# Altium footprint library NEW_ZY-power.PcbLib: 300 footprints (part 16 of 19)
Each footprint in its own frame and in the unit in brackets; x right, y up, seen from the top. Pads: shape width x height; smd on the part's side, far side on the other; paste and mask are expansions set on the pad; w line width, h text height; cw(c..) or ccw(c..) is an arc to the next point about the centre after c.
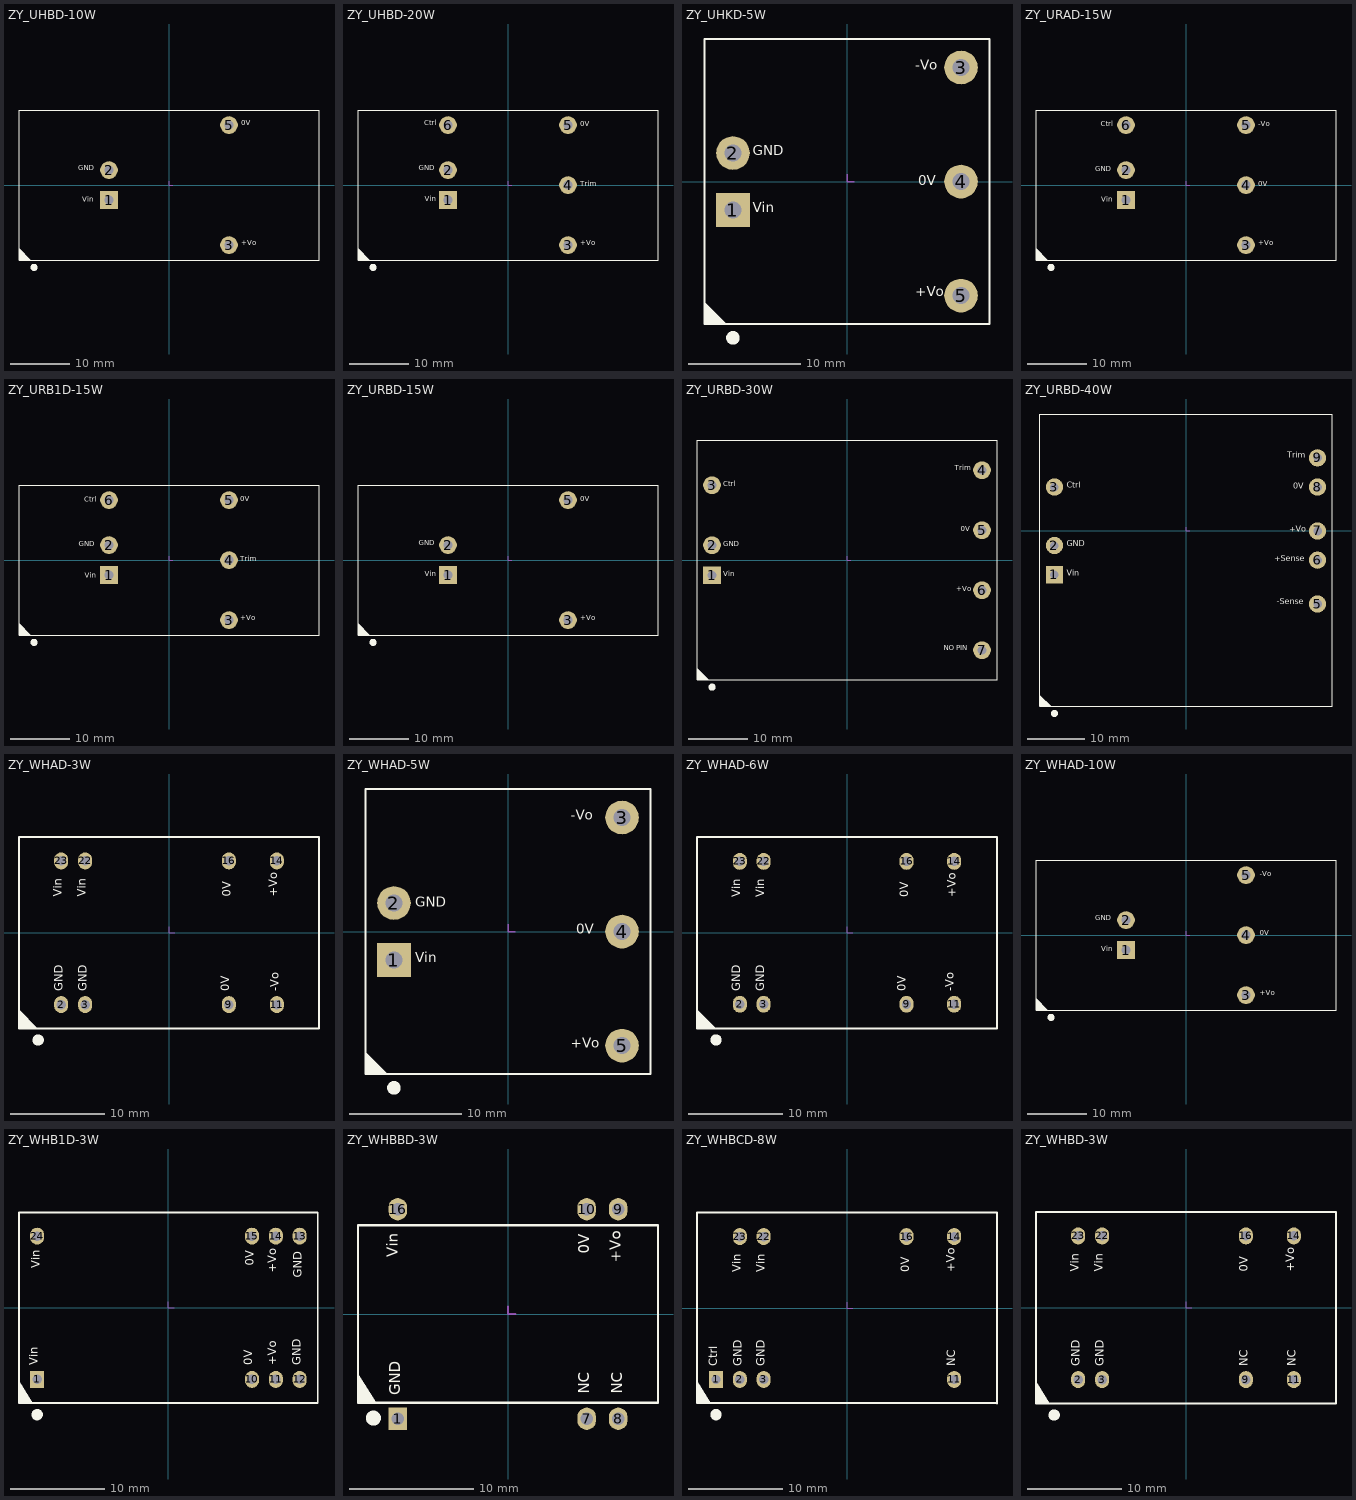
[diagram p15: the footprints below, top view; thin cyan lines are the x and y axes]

## ZY_UHBD-10W [mm]
height 12.7
pads (4):
  rect 3x3 hole 1.5: 1(-10.16,-2.54)
  round 3 hole 1.5: 2(-10.16,2.54) 3(10.16,-10.16) 5(10.16,10.16)
Top Overlay:
  circle w1: c-22.86,-13.925 r0.1
  region: -25.4,-12.7 -23.425,-12.7 -25.4,-10.725
  lines w0.2: -25.4,-12.7 -25.4,12.7 25.4,12.7 25.4,-12.7 -25.4,-12.7
  text "Vin" at -14.732,-3.175 h1.52
  text "GND" at -15.368,2.159 h1.52
  text "+Vo" at 12.192,-10.541 h1.52
  text "0V" at 12.192,9.779 h1.52
Mechanical 15:
  lines w0.127: 0,0.635 0,0 0.635,0

## ZY_UHBD-20W [mm]
pads (6):
  rect 3x3 hole 1.5: 1(-10.16,-2.54)
  round 3 hole 1.5: 2(-10.16,2.54) 3(10.16,-10.16) 4(10.16,0) 5(10.16,10.16) 6(-10.16,10.16)
Top Overlay:
  circle w1: c-22.86,-13.925 r0.1
  region: -25.4,-12.7 -23.425,-12.7 -25.4,-10.725
  lines w0.2: -25.4,-12.7 -25.4,12.7 25.4,12.7 25.4,-12.7 -25.4,-12.7
  text "+Vo" at 12.192,-10.541 h1.52
  text "0V" at 12.192,9.652 h1.52
  text "GND" at -15.113,2.159 h1.52
  text "Vin" at -14.103,-3.048 h1.52
  text "Trim" at 12.192,-0.508 h1.52
  text "Ctrl" at -14.187,9.779 h1.52
Mechanical 15:
  lines w0.127: 0,0.635 0,0 0.635,0

## ZY_UHKD-5W [mm]
pads (5):
  rect 3x3 hole 1.5: 1(-10.16,-2.54)
  round 3 hole 1.5: 2(-10.16,2.54) 3(10.16,10.16) 4(10.16,0) 5(10.16,-10.16)
Top Overlay:
  circle w1: c-10.16,-13.925 r0.1
  region: -12.7,-12.7 -10.725,-12.7 -12.7,-10.725
  lines w0.2: -12.7,-12.7 -12.7,12.7 12.7,12.7 12.7,-12.7 -12.7,-12.7
  text "Vin" at -8.382,-3.048 h1.52
  text "GND" at -8.382,2.032 h1.52
  text "0V" at 6.35,-0.635 h1.52
  text "-Vo" at 6.096,9.652 h1.52
  text "+Vo" at 6.096,-10.541 h1.52
Mechanical 15:
  lines w0.127: 0,0.635 0,0 0.635,0

## ZY_URAD-15W [mm]
pads (6):
  rect 3x3 hole 1.5: 1(-10.16,-2.54)
  round 3 hole 1.5: 2(-10.16,2.54) 3(10.16,-10.16) 4(10.16,0) 5(10.16,10.16) 6(-10.16,10.16)
Top Overlay:
  circle w1: c-22.86,-13.925 r0.1
  region: -25.4,-12.7 -23.425,-12.7 -25.4,-10.725
  lines w0.2: -25.4,-12.7 -25.4,12.7 25.4,12.7 25.4,-12.7 -25.4,-12.7
  text "+Vo" at 12.192,-10.541 h1.52
  text "-Vo" at 12.192,9.652 h1.52
  text "GND" at -15.368,2.032 h1.52
  text "Vin" at -14.358,-3.175 h1.52
  text "0V" at 12.192,-0.508 h1.52
  text "Ctrl" at -14.443,9.652 h1.52
Mechanical 15:
  lines w0.127: 0,0.635 0,0 0.635,0

## ZY_URB1D-15W [mm]
pads (6):
  rect 3x3 hole 1.5: 1(-10.16,-2.54)
  round 3 hole 1.5: 2(-10.16,2.54) 3(10.16,-10.16) 4(10.16,0) 5(10.16,10.16) 6(-10.16,10.16)
Top Overlay:
  circle w1: c-22.86,-13.925 r0.1
  region: -25.4,-12.7 -23.425,-12.7 -25.4,-10.725
  lines w0.2: -25.4,-12.7 25.4,-12.7 25.4,12.7 -25.4,12.7 -25.4,-12.7
  text "Ctrl" at -14.316,9.525 h1.52
  text "Trim" at 12.065,-0.508 h1.52
  text "Vin" at -14.231,-3.302 h1.52
  text "GND" at -15.241,2.032 h1.52
  text "0V" at 12.065,9.652 h1.52
  text "+Vo" at 12.065,-10.541 h1.52
Mechanical 15:
  lines w0.127: 0,0.635 0,0 0.635,0

## ZY_URBD-15W [mm]
pads (4):
  rect 3x3 hole 1.5: 1(-10.16,-2.54)
  round 3 hole 1.5: 2(-10.16,2.54) 3(10.16,-10.16) 5(10.16,10.16)
Top Overlay:
  circle w1: c-22.86,-13.925 r0.1
  region: -25.4,-12.7 -23.425,-12.7 -25.4,-10.725
  lines w0.2: -25.4,-12.7 -25.4,12.7 25.4,12.7 25.4,-12.7 -25.4,-12.7
  text "+Vo" at 12.192,-10.541 h1.52
  text "0V" at 12.192,9.652 h1.52
  text "GND" at -15.114,2.159 h1.52
  text "Vin" at -14.104,-3.048 h1.52
Mechanical 15:
  lines w0.127: 0,0.635 0,0 0.635,0

## ZY_URBD-30W [mm]
height 12.5
pads (7):
  rect 3x3 hole 1.5: 1(-22.86,-2.54)
  round 3 hole 1.5: 2(-22.86,2.54) 3(-22.86,12.7) 4(22.86,15.24) 5(22.86,5.08) 6(22.86,-5.08) 7(22.86,-15.24)
Top Overlay:
  circle w1: c-22.86,-21.505 r0.1
  region: -25.4,-20.28 -23.425,-20.28 -25.4,-18.305
  lines w0.2: -25.4,-20.28 25.4,-20.28 25.4,20.32 -25.4,20.32 -25.4,-20.28
  text "Vin" at -20.955,-3.028 h1.52
  text "+Vo" at 18.523,-5.568 h1.52
  text "0V" at 19.263,4.592 h1.52
  text "Ctrl" at -20.955,12.212 h1.52
  text "Trim" at 18.255,14.879 h1.52
  text "GND" at -20.955,2.052 h1.52
  text "NO PIN" at 16.383,-15.621 h1.52
Mechanical 15:
  lines w0.127: 0,0.635 0,0 0.635,0

## ZY_URBD-40W [mm]
height 13.8
pads (8):
  rect 3x3 hole 1.5: 1(-22.86,-7.62)
  round 3 hole 1.5: 2(-22.86,-2.54) 3(-22.86,7.62) 5(22.86,-12.7) 6(22.86,-5.08) 7(22.86,0) 8(22.86,7.62) 9(22.86,12.7)
Top Overlay:
  circle w1: c-22.86,-31.705 r0.1
  region: -25.4,-30.48 -23.425,-30.48 -25.4,-28.505
  lines w0.2: -25.4,-30.48 -25.4,20.32 25.4,20.32 25.4,-30.48 -25.4,-30.48
  text "-Sense" at 15.731,-13.081 h1.78
  text "GND" at -20.701,-3.028 h1.78
  text "Trim" at 17.614,12.339 h1.78
  text "Ctrl" at -20.701,7.132 h1.78
  text "+Vo" at 17.926,-0.488 h1.78
  text "+Sense" at 15.367,-5.588 h1.78
  text "Vin" at -20.701,-8.108 h1.78
  text "0V" at 18.663,7.005 h1.78
Mechanical 15:
  lines w0.127: 0,0.635 0,0 0.635,0

## ZY_WHAD-3W [mm] "宽压输入隔离稳压双输出电源模块"
height 9.5
pads (8):
  oval 1.5x1.8 hole 1: 2(-11.43,-7.62) 3(-8.89,-7.62) 9(6.35,-7.62) 11(11.43,-7.62) 14(11.43,7.62) 16(6.35,7.62) 22(-8.89,7.62) 23(-11.43,7.62)
Top Overlay:
  circle w1: c-13.87,-11.375 r0.1
  region: -15.9,-10.15 -13.925,-10.15 -15.9,-8.175
  lines w0.2: -15.9,-10.15 15.9,-10.15 15.9,10.15 -15.9,10.15 -15.9,-10.15
  text "Vin" at -11.049,3.81 h1.52
  text "Vin" at -8.509,3.81 h1.52
  text "0V" at 6.858,3.81 h1.52
  text "+Vo" at 11.811,3.81 h1.52
  text "-Vo" at 11.938,-6.223 h1.52
  text "0V" at 6.731,-6.223 h1.52
  text "GND" at -8.382,-6.223 h1.52
  text "GND" at -10.922,-6.223 h1.52
Mechanical 15:
  lines w0.127: 0,0.635 0,0 0.635,0

## ZY_WHAD-5W [mm]
height 11.7
pads (5):
  rect 3x3 hole 1.5: 1(-10.16,-2.54)
  round 3 hole 1.5: 2(-10.16,2.54) 3(10.16,10.16) 4(10.16,0) 5(10.16,-10.16)
Top Overlay:
  circle w1: c-10.16,-13.925 r0.1
  region: -12.7,-12.7 -10.725,-12.7 -12.7,-10.725
  lines w0.2: -12.7,-12.7 12.7,-12.7 12.7,12.7 -12.7,12.7 -12.7,-12.7
  text "-Vo" at 5.588,9.652 h1.52
  text "+Vo" at 5.588,-10.668 h1.52
  text "Vin" at -8.255,-3.048 h1.52
  text "GND" at -8.255,1.905 h1.52
  text "0V" at 6.096,-0.508 h1.52
Mechanical 15:
  lines w0.127: 0,0.635 0,0 0.635,0

## ZY_WHAD-6W [mm]
height 10.5
pads (8):
  oval 1.5x1.8 hole 1: 2(-11.43,-7.62) 3(-8.89,-7.62) 9(6.35,-7.62) 11(11.43,-7.62) 14(11.43,7.62) 16(6.35,7.62) 22(-8.89,7.62) 23(-11.43,7.62)
Top Overlay:
  circle w1: c-13.97,-11.425 r0.1
  region: -16,-10.2 -14.025,-10.2 -16,-8.225
  lines w0.2: -16,-10.2 16,-10.2 16,10.2 -16,10.2 -16,-10.2
  text "0V" at 6.858,3.81 h1.52
  text "+Vo" at 11.938,3.81 h1.52
  text "-Vo" at 11.684,-6.223 h1.52
  text "Vin" at -8.509,3.81 h1.52
  text "Vin" at -11.049,3.81 h1.52
  text "GND" at -8.509,-6.223 h1.52
  text "GND" at -11.049,-6.223 h1.52
  text "0V" at 6.604,-6.223 h1.52
Mechanical 15:
  lines w0.127: 0,0.635 0,0 0.635,0

## ZY_WHAD-10W [mm]
pads (5):
  rect 3x3 hole 1.5: 1(-10.16,-2.54)
  round 3 hole 1.5: 2(-10.16,2.54) 3(10.16,-10.16) 4(10.16,0) 5(10.16,10.16)
Top Overlay:
  circle w1: c-22.86,-13.925 r0.1
  region: -25.4,-12.7 -23.425,-12.7 -25.4,-10.725
  lines w0.2: -25.4,-12.7 -25.4,12.7 25.4,12.7 25.4,-12.7 -25.4,-12.7
  text "-Vo" at 12.446,9.652 h1.52
  text "+Vo" at 12.446,-10.541 h1.52
  text "0V" at 12.446,-0.381 h1.52
  text "GND" at -15.368,2.159 h1.52
  text "Vin" at -14.358,-3.048 h1.52
Mechanical 15:
  lines w0.127: 0,0.635 0,0 0.635,0

## ZY_WHB1D-3W [mm]
height 10.5
pads (8):
  rect 1.5x1.8 hole 1: 1(-13.97,-7.62)
  oval 1.5x1.8 hole 1: 10(8.89,-7.62) 11(11.43,-7.62) 12(13.97,-7.62) 13(13.97,7.62) 14(11.43,7.62) 15(8.89,7.62) 24(-13.97,7.62)
Top Overlay:
  circle w1: c-13.97,-11.375 r0.1
  region: -15.9,-7.82 -15.9,-10.15 -14.44,-10.15
  lines w0.2: -15.9,-10.15 -15.9,10.15 15.9,10.15 15.9,-10.15 -15.9,-10.15
  text "GND" at 14.427,-6.096 h1.52
  text "Vin" at -13.36,4.185 h1.52
  text "Vin" at -13.564,-6.096 h1.52
  text "0V" at 9.246,-6.096 h1.52
  text "+Vo" at 11.811,-6.096 h1.52
  text "0V" at 9.423,4.457 h1.52
  text "+Vo" at 11.811,3.717 h1.52
  text "GND" at 14.503,3.175 h1.52
Mechanical 15:
  lines w0.127: 0,0.635 0,0 0.635,0

## ZY_WHBBD-3W [mm]
height 4.6
pads (6):
  rect 1.5x1.8 hole 1: 1(-8.89,-8.45)
  oval 1.5x1.8 hole 1: 7(6.35,-8.45) 8(8.89,-8.45) 9(8.89,8.45) 10(6.35,8.45) 16(-8.89,8.45)
Top Overlay:
  circle w1: c-10.863,-8.4 r0.1
  region: -12.1,-4.845 -12.1,-7.175 -10.64,-7.175
  lines w0.2: -12.1,-7.175 12.1,-7.175 12.1,7.175 -12.1,7.175 -12.1,-7.175
  text "NC" at 9.525,-6.415 h1.52
  text "GND" at -8.382,-6.542 h1.52
  text "Vin" at -8.56,4.597 h1.52
  text "0V" at 6.858,4.869 h1.52
  text "+Vo" at 9.398,4.129 h1.52
  text "NC" at 6.858,-6.415 h1.52
Mechanical 15:
  lines w0.127: 0,0.635 0,0 0.635,0

## ZY_WHBCD-8W [mm]
height 11
pads (8):
  rect 1.5x1.8 hole 1: 1(-13.97,-7.62)
  oval 1.5x1.8 hole 1: 2(-11.43,-7.62) 3(-8.89,-7.62) 11(11.43,-7.62) 14(11.43,7.62) 16(6.35,7.62) 22(-8.89,7.62) 23(-11.43,7.62)
Top Overlay:
  circle w1: c-13.97,-11.375 r0.1
  region: -16,-7.82 -16,-10.15 -14.54,-10.15
  lines w0.2: 16,-10.2 16,10.2 -16,10.2 -16,-10.15 16,-10.15
  text "GND" at -10.897,-6.223 h1.52
  text "+Vo" at 11.811,3.81 h1.52
  text "0V" at 6.985,3.81 h1.52
  text "Ctrl" at -13.538,-6.223 h1.52
  text "NC" at 11.887,-6.223 h1.52
  text "Vin" at -8.433,3.81 h1.52
  text "Vin" at -10.998,3.81 h1.52
  text "GND" at -8.458,-6.223 h1.52
Mechanical 15:
  lines w0.127: 0,0.635 0,0 0.635,0

## ZY_WHBD-3W [mm] "宽压输入隔离稳压单输出电源模块"
height 9.5
pads (8):
  oval 1.5x1.8 hole 1: 2(-11.43,-7.62) 3(-8.89,-7.62) 9(6.35,-7.62) 11(11.43,-7.62) 14(11.43,7.62) 16(6.35,7.62) 22(-8.89,7.62) 23(-11.43,7.62)
Top Overlay:
  circle w1: c-13.97,-11.375 r0.1
  region: -15.9,-7.82 -15.9,-10.15 -14.44,-10.15
  lines w0.2: -15.9,-10.15 15.9,-10.15 15.9,10.15 -15.9,10.15 -15.9,-10.15
  text "+Vo" at 11.811,3.81 h1.52
  text "0V" at 6.858,3.81 h1.52
  text "Vin" at -8.509,3.81 h1.52
  text "Vin" at -11.049,3.81 h1.52
  text "GND" at -8.382,-6.223 h1.52
  text "GND" at -10.922,-6.223 h1.52
  text "NC" at 6.858,-6.223 h1.52
  text "NC" at 11.938,-6.223 h1.52
Mechanical 15:
  lines w0.127: 0,0.635 0,0 0.635,0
